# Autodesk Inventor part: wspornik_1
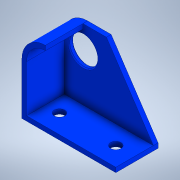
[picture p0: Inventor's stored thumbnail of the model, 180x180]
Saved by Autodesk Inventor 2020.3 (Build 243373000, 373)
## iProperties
Created: 2021-01
Part Number: wspornik_1
Material: Ogólny
Document SubType Name: Modeling
Designer: Dom
Density: 1 g/cm^3
Appearance: Domyślna
Author: Dom
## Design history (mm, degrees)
sketch "Szkic1"
  geometry: L1 (0, 0)-(100, 0); L2 (100, 0)-(100, 5); L3 (50, 80)-(25, 80); L4 (0, 55)-(0, 0); L5 (50, 80)-(100, 5); C1 r 15 at (25, 55); A1 r 25 centre (25, 55) between (25, 80) and (0, 55)
  constraints: 10 end point, 2 centre point, 2 parallel, 2 point on circle, 1 coincident, 1 horizontal, 1 perpendicular, 1 tangent
  dimensions: "d4" = 30 diameter of C1; "d5" = 25 distance from line of L4 C1.centre; "d6" = 55 distance from line of L1 C1.centre; "d7" = 5 distance of L2.end L1.end; "d8" = 50 diameter of A1
extrude "Wyciągnięcie proste1" new body sketch "Szkic1" distance "d9" = 5; taper "d10" = 0 deg
sketch "Szkic2"
  geometry: L1 (0, 55)-(0, 0) reference; L2 (100, 0)-(100, 5) reference; L3 (0, 0)-(100, 0); L4 (100, 0)-(100, 5); L5 (100, 5)-(0, 5); L6 (0, 5)-(0, 0); 2 further points
  constraints: 8 end point, 2 parallel, 1 horizontal, 1 perpendicular
extrude "Wyciągnięcie proste2" join sketch "Szkic2" distance "d11" = 40; taper "d12" = 0 deg
sketch "Szkic3"
  geometry: L1 (0, 0)-(0, -40) reference; L2 (100, 0)-(100, -40) reference; C1 r 5.5 at (20, -20); C2 r 5.5 at (80, -20); 2 further points
  constraints: 2 centre point, 2 horizontal alignment, 1 equal radius, 1 midpoint
  dimensions: "d13" = 11 diameter of C1; "d14" = 20 distance from line of L1 C1.centre; "d17" = 20 distance from line of C2.centre L2 (= d14)
extrude "Wyciągnięcie proste3" cut sketch "Szkic3" extent not by distance; stored distance "d15" = 60; taper "d16" = 0 deg
sketch "Szkic4"
  geometry: L1 (0, 55)-(0, 5) reference; L2 (5, 55)-(5, 5); L3 (50, 80)-(25, 80) reference; L4 (25, 80)-(25, 75); L5 (100, 5)-(0, 5) reference; C1 r 15 at (25, 55) reference; A1 r 25 centre (25, 55) between (25, 80) and (0, 55) reference; A2 r 25 centre (25, 55) between (25, 80) and (0, 55) reference; A3 r 20 centre (25, 55) between (25, 75) and (5, 55); 1 further point
  constraints: 4 end point, 2 point on circle, 1 centre point, 1 coincident, 1 parallel, 1 perpendicular
  dimensions: "d20" = 5 distance between parallel lines of L1 L2
extrude "Wyciągnięcie proste4" join sketch "Szkic4" distance "d18" = 40; taper "d19" = 0 deg
chamfer "Faza1" distance "d21" = 1; stored, may be unused: second distance "d22" = 2, angle "d23" = 45 deg
node "Bryła1"
